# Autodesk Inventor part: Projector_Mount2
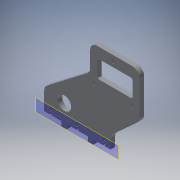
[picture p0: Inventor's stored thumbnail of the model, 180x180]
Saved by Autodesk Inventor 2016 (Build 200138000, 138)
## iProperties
Created: 2015-11
Part Number: Projector_Mount2
Material: Generic
Document SubType Name: Modeling
Designer: John
Density: 1 g/cm^3
Appearance: Default
Author: John
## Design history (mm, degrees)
sketch "Sketch1"
  geometry: L1 (-77.625, 0)-(-72.375, 0) reference; L2 (-45, 0)-(-30, 0) reference; L3 (-2.625, 0)-(2.625, 0) reference; L4 (30, 0)-(45, 0) reference; L5 (72.375, 0)-(77.625, 0) reference; L6 (-45, 0)-(-30, 0); L7 (-30, 0)-(-30, -12.7); L8 (-30, -12.7)-(-45, -12.7); L9 (-45, -12.7)-(-45, 0); L10 (30, 0)-(45, 0); L11 (45, 0)-(45, -12.7); L12 (45, -12.7)-(30, -12.7); L13 (30, -12.7)-(30, 0); L14 (-2.625, 0)-(2.625, 0); L15 (2.625, 0)-(2.625, 20); L16 (2.625, 20)-(-2.625, 20); L17 (-2.625, 20)-(-2.625, 0); L18 (72.375, 0)-(77.625, 0); L19 (77.625, 0)-(77.625, 20); L20 (77.625, 20)-(72.375, 20); L21 (72.375, 20)-(72.375, 0); L22 (-77.625, 0)-(-72.375, 0); L23 (-72.375, 0)-(-72.375, 20); L24 (-72.375, 20)-(-77.625, 20); L25 (-77.625, 20)-(-77.625, 0); L26 (-79, 14)-(-71, 14); L27 (-71, 14)-(-71, 7); L28 (-71, 7)-(-79, 7); L29 (-79, 7)-(-79, 14); L30 (-4, 14)-(4, 14); L31 (4, 14)-(4, 7); L32 (4, 7)-(-4, 7); L33 (-4, 7)-(-4, 14); L34 (71, 14)-(79, 14); L35 (79, 14)-(79, 7); L36 (79, 7)-(71, 7); L37 (71, 7)-(71, 14); 9 further points
  constraints: 64 end point, 16 parallel, 8 horizontal, 8 perpendicular, 6 equal length, 6 midpoint, 3 point on line, 3 vertical alignment, 1 other
  dimensions: "d0" = 12.7 distance of L2.end L7.end; "d1" = 20 distance of L1.end L23.end; "d2" = 7 distance of the line from the sketch origin of L28; "d3" = 7 distance of L26.end L27.end; "d4" = 8 distance of L26.start L26.end
  node "Reference1"
  node "Reference2"
  node "Reference3"
  node "Reference4"
  node "Reference5"
  node "Reference6"
workplane "Work Plane1"
sketch "Sketch2"
  geometry: L1 (94, 0)-(-94, 0); L2 (-94, 0)-(-94, 35); L3 (-94, 35)-(94, 35); L4 (94, 35)-(94, 0); L5 (94, 35)-(-36, 135); L6 (-36, 135)-(-36, 235); L7 (-36, 235)-(-176, 235); L8 (-176, 235)-(-176, 110); L9 (-176, 110)-(-94, 35); L10 (-106.55, 0)-(106.55, 0) reference; C1 r 1.75 at (-108.563, 221.95) reference; C2 r 1.75 at (-163.613, 140.45) reference; C3 r 1.75 at (-53.563, 140.45) reference; C4 r 1.75 at (-156.05, 143.5); C5 r 1.75 at (-46, 143.5); C6 r 1.75 at (-101, 225); 3 further points
  constraints: 18 end point, 3 centre point, 3 perpendicular, 2 equal radius, 2 parallel, 2 point on line, 1 horizontal, 1 horizontal alignment, 1 vertical
  dimensions: "d6" = 200 distance between parallel lines of L3 L7; "d7" = 35 distance between parallel lines of L1 L3; "d8" = 110.05 distance of C3.centre C2.centre (derived); "d9" = 55 horizontal distance of C3.centre C1.centre (derived); "d10" = 81.5 vertical distance of C3.centre C1.centre (derived); "d11" = 110.05 distance of C4.centre C5.centre (= d8); "d12" = 55 horizontal distance of C5.centre C6.centre (= d9); "d13" = 81.5 vertical distance of C5.centre C6.centre (= d10); "d14" = 10 distance from line of L7 C6.centre; "d15" = 3.5 diameter of C4; "d16" = 10 distance from line of L6 C5.centre; "d17" = 130 distance between parallel lines of L4 L6; "d18" = 15 distance from line of point (79, 14) L4; "d19" = 140 distance of L6.end L7.end; "d20" = 125 distance of L7.end L8.end; "d21" = 100 distance of L5.end L6.end; "d22" = 15 distance from line of point (-79, 14) L2
extrude "Extrusion1" new body sketch "Sketch2" distance "d23" = 12.7; taper "d24" = 0 deg
fillet "Fillet1" dims "d25" = 20
sketch "Sketch3"
  geometry: L1 (-86.194, -41.004)-(28.194, -128.996) reference; L2 (36, -144.848)-(36, -215) reference; L3 (56, -235)-(156, -235) reference; L4 (176, -215)-(176, -118.811) reference; L5 (169.498, -104.053)-(100.502, -40.947) reference; L6 (94, -26.189)-(94, 0) reference; L7 (94, 0)-(-94, 0) reference; L8 (-94, 0)-(-94, -25.152) reference; L9 (156, -205)-(56, -205); L10 (56, -205)-(56, -155); L11 (56, -155)-(156, -155); L12 (156, -155)-(156, -205); L13 (101, -225)-(101, -215); L14 (102.75, -225)-(102.75, -215); L15 (99.25, -215)-(99.25, -225); L16 (156.05, -143.5)-(156.05, -133.5); L17 (157.8, -143.5)-(157.8, -133.5); L18 (154.3, -133.5)-(154.3, -143.5); L19 (46, -143.5)-(46, -133.5); L20 (47.75, -143.5)-(47.75, -133.5); L21 (44.25, -133.5)-(44.25, -143.5); C1 r 1.75 at (101, -225) reference; C2 r 1.75 at (46, -143.5) reference; C3 r 1.75 at (156.05, -143.5) reference; C4 r 1.75 at (101, -225) reference; A1 r 20 centre (-74, -25.152) between (-94, -25.152) and (-86.194, -41.004) reference; A2 r 20 centre (16, -144.848) between (36, -144.848) and (28.194, -128.996) reference; A3 r 20 centre (56, -215) between (36, -215) and (56, -235) reference; A4 r 20 centre (156, -215) between (156, -235) and (176, -215) reference; A5 r 20 centre (156, -118.811) between (176, -118.811) and (169.498, -104.053) reference; A6 r 20 centre (114, -26.189) between (94, -26.189) and (100.502, -40.947) reference; A7 r 1.75 centre (101, -225) between (99.25, -225) and (102.75, -225); A8 r 1.75 centre (101, -215) between (102.75, -215) and (99.25, -215); A9 r 1.75 centre (156.05, -143.5) between (154.3, -143.5) and (157.8, -143.5); A10 r 1.75 centre (156.05, -133.5) between (157.8, -133.5) and (154.3, -133.5); A11 r 1.75 centre (46, -143.5) between (44.25, -143.5) and (47.75, -143.5); A12 r 1.75 centre (46, -133.5) between (47.75, -133.5) and (44.25, -133.5); 4 further points
  constraints: 32 end point, 12 point on circle, 12 tangent, 9 parallel, 6 centre point, 3 equal radius, 3 midpoint, 1 horizontal, 1 perpendicular, 1 vertical
  dimensions: "d26" = 10 distance of L16.start L16.end; "d29" = 10 distance from line of L13.end L9; "d30" = 20 distance between parallel lines of L2 L10; "d31" = 20 distance between parallel lines of L4 L12; "d32" = 50 distance of L11.end L9.start
extrude "Extrusion2" cut sketch "Sketch3" stored distance "d27" = 12.7; taper "d28" = 0 deg
fillet "Fillet2" dims "d33" = 5
extrude "Extrusion3" cut sketch "Sketch1" stored distance "d34" = 12.7; taper "d35" = 0 deg
sketch "Sketch4"
  geometry: L1 (-30, 12.7)-(-30, 0) reference; L2 (-45, 0)-(-45, 12.7) reference; L3 (-45, 12.7)-(-30, 12.7) reference; L4 (-30, 0)-(-45, 0) reference; L5 (30, 0)-(30, 12.7) reference; L6 (45, 12.7)-(45, 0) reference; L7 (30, 12.7)-(45, 12.7) reference; L8 (45, 0)-(30, 0) reference; 1 further point
extrude "Extrusion4" join sketch "Sketch4" stored distance "d36" = 12.7; taper "d37" = 0 deg
node "Direct Edit1"
node "Direct Edit2"
sketch "Sketch5"
  geometry: L1 (2.5, 0)-(2.5, -7) reference; L2 (2.5, -7)-(4, -7) reference; L3 (4, -7)-(4, -14) reference; L4 (4, -14)-(2.5, -14) reference; L5 (2.5, -14)-(2.5, -20) reference; L6 (2.5, -20)-(-2.5, -20) reference; L7 (-2.5, -20)-(-2.5, -14) reference; L8 (-2.5, -14)-(-4, -14) reference; L9 (-4, -14)-(-4, -7) reference; L10 (-4, -7)-(-2.5, -7) reference; L11 (-2.5, -7)-(-2.5, 0) reference; L12 (-2.5, 0)-(-30.125, 0) reference; L13 (-30.125, 12.7)-(-30.125, 0) reference; L14 (-44.875, 12.7)-(-30.125, 12.7) reference; L15 (-44.875, 0)-(-44.875, 12.7) reference; L16 (-44.875, 0)-(-72.5, 0) reference; L17 (-72.5, 0)-(-72.5, -7) reference; L18 (-72.5, -7)-(-71, -7) reference; L19 (-71, -7)-(-71, -14) reference; L20 (-71, -14)-(-72.5, -14) reference; L21 (-72.5, -14)-(-72.5, -20) reference; L22 (-72.5, -20)-(-77.5, -20) reference; L23 (-77.5, -20)-(-77.5, -14) reference; L24 (-77.5, -14)-(-79, -14) reference; L25 (-79, -14)-(-79, -7) reference; L26 (-79, -7)-(-77.5, -7) reference; L27 (-77.5, -7)-(-77.5, 0) reference; L28 (-77.5, 0)-(-94, 0) reference; L29 (-94, 0)-(-94, -25.152) reference; L30 (-86.194, -41.004)-(28.194, -128.996) reference; L31 (36, -144.848)-(36, -215) reference; L32 (56, -235)-(156, -235) reference; L33 (176, -215)-(176, -118.811) reference; L34 (169.498, -104.053)-(100.502, -40.947) reference; L35 (94, -26.189)-(94, 0) reference; L36 (94, 0)-(77.5, 0) reference; L37 (77.5, 0)-(77.5, -7) reference; L38 (77.5, -7)-(79, -7) reference; L39 (79, -7)-(79, -14) reference; L40 (79, -14)-(77.5, -14) reference; L41 (77.5, -14)-(77.5, -20) reference; L42 (77.5, -20)-(72.5, -20) reference; L43 (72.5, -20)-(72.5, -14) reference; L44 (72.5, -14)-(71, -14) reference; L45 (71, -14)-(71, -7) reference; L46 (71, -7)-(72.5, -7) reference; L47 (72.5, -7)-(72.5, 0) reference; L48 (72.5, 0)-(44.875, 0) reference; L49 (44.875, 12.7)-(44.875, 0) reference; L50 (30.125, 12.7)-(44.875, 12.7) reference; L51 (30.125, 0)-(30.125, 12.7) reference; L52 (30.125, 0)-(2.5, 0) reference; L53 (156, -160)-(156, -200) reference; L54 (151, -205)-(61, -205) reference; L55 (56, -200)-(56, -160) reference; L56 (61, -155)-(151, -155) reference; L57 (47.75, -133.5)-(47.75, -143.5) reference; L58 (44.25, -143.5)-(44.25, -133.5) reference; L59 (102.75, -215)-(102.75, -225) reference; L60 (99.25, -225)-(99.25, -215) reference; L61 (157.8, -133.5)-(157.8, -143.5) reference; L62 (154.3, -143.5)-(154.3, -133.5) reference; C1 r 19.05 at (-36.55, -48.25); A1 r 20 centre (-74, -25.152) between (-94, -25.152) and (-86.194, -41.004) reference; A2 r 20 centre (16, -144.848) between (36, -144.848) and (28.194, -128.996) reference; A3 r 20 centre (56, -215) between (36, -215) and (56, -235) reference; A4 r 20 centre (156, -215) between (156, -235) and (176, -215) reference; A5 r 20 centre (156, -118.811) between (176, -118.811) and (169.498, -104.053) reference; A6 r 20 centre (114, -26.189) between (94, -26.189) and (100.502, -40.947) reference; A7 r 5 centre (151, -200) between (151, -205) and (156, -200) reference; A8 r 5 centre (61, -200) between (56, -200) and (61, -205) reference; A9 r 5 centre (61, -160) between (61, -155) and (56, -160) reference; A10 r 5 centre (151, -160) between (156, -160) and (151, -155) reference; A11 r 1.75 centre (46, -143.5) between (44.25, -143.5) and (47.75, -143.5) reference; A12 r 1.75 centre (46, -133.5) between (47.75, -133.5) and (44.25, -133.5) reference; A13 r 1.75 centre (101, -225) between (99.25, -225) and (102.75, -225) reference; A14 r 1.75 centre (101, -215) between (102.75, -215) and (99.25, -215) reference; A15 r 1.75 centre (156.05, -143.5) between (154.3, -143.5) and (157.8, -143.5) reference; A16 r 1.75 centre (156.05, -133.5) between (157.8, -133.5) and (154.3, -133.5) reference; 1 further point
  constraints: 1 centre point
  dimensions: "d44" = 95.25 vertical distance of C1.centre A11.centre; "d45" = 82.55 horizontal distance of A11.centre C1.centre; "d46" = 38.1 diameter of C1
extrude "Extrusion5" cut sketch "Sketch5" stored distance "d47" = 12.7; taper "d48" = 0 deg
node "Direct Edit3"
node "Direct Edit4"
body "Solid1"
node "Reference7"
node "Reference8"
node "Reference9"
node "Projected Loop1"
node "Projected Loop2"
feature "耀쀵"
move_body "Move1" dims "d40" = 0.125
move_body "Move2" dims "d43" = 0.125
move_body "Move3" dims "d51" = 10
move_body "Move4" dims "d54" = 10
other parameters: "d5" = 42, "d38" = 0, "d39" = 0, "d41" = 0, "d42" = 0, "d49" = 0, "d50" = 0, "d52" = 0, "d53" = 0
